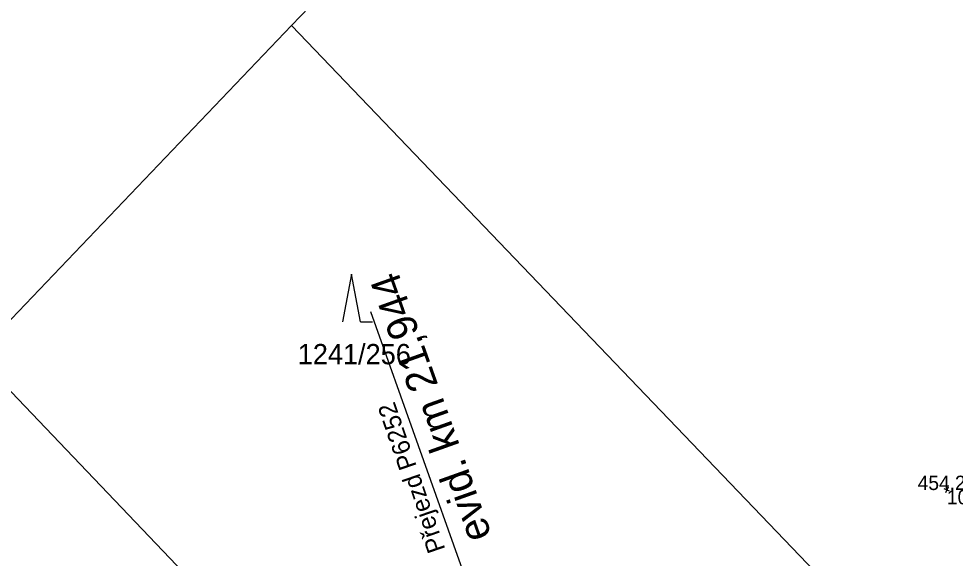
# Model space of a CAD drawing. Extents: x -776734 to -748832, y -1118122 to -976986.
# Drawn here: x -751572.3 to -751493.8, y -1114796.8 to -1114751.6 of the extents above; entities that cross this region are included whole.
import ezdxf

# ---------------------------------------------------------------- set-up
doc = ezdxf.new("R2010")
doc.units = 0
for name, color, linetype in [('KM_Hranice parcel', 7, 'Continuous'), ('KM_Parcelní čísla', 7, 'Continuous'), ('KM_Značky kultur', 7, 'Continuous'), ('SŽG Vrstva 4', 7, 'Continuous'), ('SŽG Vrstva 49', 7, 'Continuous'), ('SŽG Vrstva 60', 7, 'Continuous'), ('SŽG Vrstva 61', 7, 'Continuous')]:
    doc.layers.add(name, color=color, linetype=linetype)

msp = doc.modelspace()

# ---------------------------------------------------------------- linework, layer by layer
at = {"layer": 'KM_Hranice parcel'}
for p, q in [((-751549.39, -1114752.11), (-751521.01, -1114722.63)), ((-751575.82, -1114779.78), (-751549.39, -1114752.11)), ((-751501.68, -1114801.88), (-751549.39, -1114752.11)), ((-751554.36, -1114802.22), (-751575.82, -1114779.78))]:
    msp.add_line(p, q, dxfattribs=at)
at = {"layer": 'KM_Značky kultur'}
for p, q in [((-751544.37, -1114772.96), (-751545.12, -1114776.96)), ((-751543.62, -1114776.96), (-751544.37, -1114772.96)), ((-751543.62, -1114776.96), (-751542.624, -1114776.96))]:
    msp.add_line(p, q, dxfattribs=at)
at = {"layer": 'SŽG Vrstva 4'}
msp.add_line((-751527.0562, -1114820.1567), (-751542.756, -1114776.116), dxfattribs=at)
at = {"layer": 'SŽG Vrstva 49'}
for p, q in [((-751494.2272, -1114791.1584), (-751494.6768, -1114790.9396)), ((-751494.3426, -1114790.8242), (-751494.5614, -1114791.2738))]:
    msp.add_line(p, q, dxfattribs=at)
at = {"layer": 'SŽG Vrstva 60'}
msp.add_line((-751494.452, -1114791.049), (-751494.452, -1114791.049), dxfattribs=at)

# ---------------------------------------------------------------- texts
at = {"layer": 'KM_Parcelní čísla'}
msp.add_text('1241/256', height=1.7, dxfattribs=at).set_placement((-751548.88, -1114780.51))
at = {"layer": 'SŽG Vrstva 4'}
for s, height, rotation, p in [('evid. km 21,944', 2.5, 109.620326, (-751532.5919, -1114794.86)), ('Přejezd P6252', 1.5, 109.008543, (-751536.4951, -1114796.0134))]:
    msp.add_text(s, height=height, rotation=rotation, dxfattribs=at).set_placement(p)
at = {"layer": 'SŽG Vrstva 60'}
msp.add_text('1007', height=1.2, dxfattribs=at).set_placement((-751494.452, -1114792.249))
at = {"layer": 'SŽG Vrstva 61'}
msp.add_text('454.264', height=1.2, dxfattribs=at).set_placement((-751496.903, -1114791.049))

doc.saveas('drawing.dxf')
